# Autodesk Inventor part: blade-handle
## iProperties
Author: Administrator
Created: 2001-01
Part Number: blade-handle
Document SubType Name: Modeling
Designer: Administrator
Control State: 0
Master: False
Checked Out: False
PropertySet Name: Design Tracking Control
Shininess: 0.0
PropertySet Name: _Private Model Information
Density: 0.0
Volumn: 0.0
Area: 0.0
PropertySet Name: Model Information
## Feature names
1. Revolution1
2. Hole1
